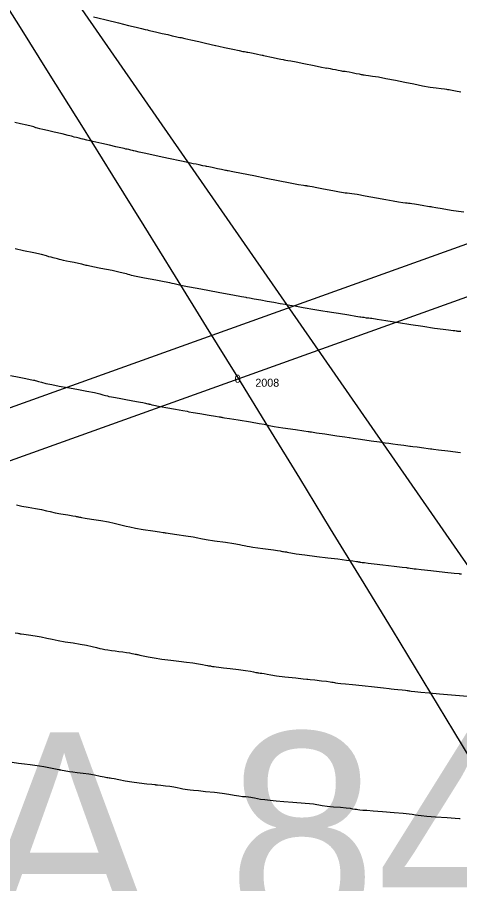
# Model space of a CAD drawing. Extents: x 74655 to 77873, y 48844 to 50507.
# Drawn here: x 75187.75 to 75194.38, y 49695.59 to 49708.57 of the extents above; entities that cross this region are included whole.
import ezdxf

# ---------------------------------------------------------------- set-up
doc = ezdxf.new("R2010")
doc.units = 0
for name, color, linetype in [('2', 7, 'Continuous'), ('24', 7, 'Continuous'), ('5', 7, 'Continuous'), ('50', 7, 'Continuous'), ('62', 7, 'Continuous'), ('7', 7, 'Continuous')]:
    doc.layers.add(name, color=color, linetype=linetype)

msp = doc.modelspace()

# ---------------------------------------------------------------- linework, layer by layer
at = {"layer": '2'}
for radius in [833.511, 829.511, 818.511]:
    msp.add_arc((74494.001, 49274.129), radius, 30.805045, 46.697858, dxfattribs=at)
at = {"layer": '5'}
msp.add_line((75166.591, 49740.588), (75280.568, 49576.243), dxfattribs=at)
at = {"layer": '50'}
for points in [[(75188.892, 49708.577), (75188.955, 49708.562), (75189.079, 49708.531), (75189.265, 49708.486), (75189.415, 49708.449), (75189.53, 49708.421), (75189.608, 49708.402), (75189.664, 49708.389), (75189.698, 49708.381), (75189.71, 49708.379), (75189.751, 49708.37), (75189.821, 49708.354), (75189.921, 49708.33), (75190.003, 49708.311), (75190.069, 49708.295), (75190.117, 49708.284), (75190.156, 49708.275), (75190.184, 49708.27), (75190.203, 49708.267), (75190.257, 49708.255), (75190.346, 49708.235), (75190.47, 49708.206), (75190.566, 49708.184), (75190.633, 49708.169), (75190.672, 49708.16), (75190.7, 49708.153), (75190.717, 49708.15), (75190.723, 49708.149), (75190.768, 49708.139), (75190.854, 49708.12), (75190.979, 49708.091), (75191.07, 49708.071), (75191.128, 49708.059), (75191.151, 49708.056), (75191.171, 49708.053), (75191.188, 49708.05), (75191.201, 49708.048), (75191.232, 49708.042), (75191.28, 49708.032), (75191.347, 49708.017), (75191.393, 49708.007), (75191.419, 49708.001), (75191.426, 49708.001), (75191.439, 49707.998), (75191.461, 49707.993), (75191.489, 49707.987), (75191.53, 49707.978), (75191.583, 49707.966), (75191.648, 49707.952), (75191.696, 49707.942), (75191.729, 49707.936), (75191.745, 49707.933), (75191.769, 49707.93), (75191.802, 49707.925), (75191.844, 49707.92), (75191.924, 49707.905), (75192.041, 49707.881), (75192.197, 49707.847), (75192.304, 49707.825), (75192.363, 49707.813), (75192.382, 49707.81)], [(75194.391, 49707.451), (75194.315, 49707.465), (75194.265, 49707.474), (75194.239, 49707.479), (75194.217, 49707.483), (75194.198, 49707.486), (75194.183, 49707.488), (75194.149, 49707.492), (75194.096, 49707.498), (75194.025, 49707.507), (75193.933, 49707.521), (75193.821, 49707.541), (75193.689, 49707.567), (75193.553, 49707.594), (75193.414, 49707.622), (75193.272, 49707.65), (75193.158, 49707.672), (75193.071, 49707.686), (75193.011, 49707.694), (75192.969, 49707.699), (75192.946, 49707.702), (75192.94, 49707.703), (75192.931, 49707.705), (75192.918, 49707.707), (75192.903, 49707.71), (75192.873, 49707.717), (75192.827, 49707.726), (75192.767, 49707.738), (75192.719, 49707.748), (75192.684, 49707.754), (75192.662, 49707.757), (75192.643, 49707.759), (75192.626, 49707.761), (75192.611, 49707.763), (75192.587, 49707.768), (75192.555, 49707.774), (75192.513, 49707.783), (75192.475, 49707.791), (75192.442, 49707.798), (75192.382, 49707.81)], [(75190.305, 49706.393), (75189.918, 49706.477), (75189.764, 49706.51), (75189.648, 49706.535), (75189.573, 49706.552), (75189.52, 49706.564), (75189.492, 49706.57), (75189.487, 49706.572), (75189.473, 49706.575), (75189.45, 49706.58), (75189.417, 49706.588), (75189.393, 49706.593), (75189.38, 49706.596), (75189.376, 49706.597), (75189.349, 49706.604), (75189.298, 49706.615), (75189.224, 49706.632), (75189.13, 49706.653), (75189.016, 49706.678), (75188.882, 49706.709), (75188.789, 49706.73), (75188.736, 49706.743), (75188.725, 49706.746), (75188.704, 49706.752), (75188.673, 49706.759), (75188.633, 49706.769), (75188.601, 49706.777), (75188.577, 49706.783), (75188.562, 49706.789), (75188.51, 49706.802), (75188.423, 49706.823), (75188.3, 49706.851), (75188.202, 49706.874), (75188.13, 49706.891), (75188.084, 49706.902), (75188.051, 49706.91), (75188.031, 49706.915), (75188.025, 49706.917), (75188.017, 49706.92), (75188.007, 49706.923), (75187.995, 49706.928), (75187.956, 49706.938), (75187.891, 49706.954), (75187.799, 49706.976), (75187.714, 49706.996)], [(75194.436, 49705.649), (75194.356, 49705.66), (75194.248, 49705.677), (75194.114, 49705.7), (75194.02, 49705.716), (75193.965, 49705.726), (75193.949, 49705.729), (75193.937, 49705.731), (75193.928, 49705.732), (75193.923, 49705.732), (75193.893, 49705.737), (75193.839, 49705.747), (75193.761, 49705.76), (75193.701, 49705.77), (75193.659, 49705.776), (75193.635, 49705.779), (75193.611, 49705.781), (75193.588, 49705.784), (75193.564, 49705.786), (75193.522, 49705.793), (75193.46, 49705.803), (75193.38, 49705.817), (75193.27, 49705.837), (75193.13, 49705.862), (75192.962, 49705.893), (75192.838, 49705.915), (75192.758, 49705.927), (75192.723, 49705.931), (75192.69, 49705.935), (75192.661, 49705.938), (75192.635, 49705.941), (75192.573, 49705.952), (75192.474, 49705.97), (75192.338, 49705.996), (75192.236, 49706.015), (75192.168, 49706.028), (75192.132, 49706.035), (75192.107, 49706.039), (75192.092, 49706.042), (75192.087, 49706.043), (75192.076, 49706.044), (75192.058, 49706.046), (75192.035, 49706.049), (75191.96, 49706.062), (75191.835, 49706.086), (75191.659, 49706.121), (75191.479, 49706.157), (75191.294, 49706.194), (75191.105, 49706.231), (75190.976, 49706.257), (75190.907, 49706.27), (75190.898, 49706.272), (75190.885, 49706.274), (75190.868, 49706.277), (75190.848, 49706.281), (75190.809, 49706.289), (75190.749, 49706.302), (75190.67, 49706.318), (75190.616, 49706.329), (75190.588, 49706.335), (75190.585, 49706.335), (75190.566, 49706.339), (75190.529, 49706.347), (75190.475, 49706.358), (75190.426, 49706.368), (75190.382, 49706.377), (75190.305, 49706.393)], [(75188.35, 49704.953), (75188.287, 49704.966), (75188.255, 49704.975), (75188.22, 49704.984), (75188.185, 49704.996), (75188.11, 49705.014), (75187.995, 49705.04), (75187.842, 49705.073), (75187.719, 49705.1)], [(75194.393, 49703.862), (75194.368, 49703.864), (75194.352, 49703.865), (75194.348, 49703.865), (75194.338, 49703.867), (75194.323, 49703.869), (75194.302, 49703.872), (75194.276, 49703.875), (75194.245, 49703.878), (75194.209, 49703.881), (75194.127, 49703.891), (75193.998, 49703.91), (75193.824, 49703.937), (75193.644, 49703.965), (75193.46, 49703.994), (75193.271, 49704.023), (75193.138, 49704.043), (75193.06, 49704.055), (75193.039, 49704.056), (75193.013, 49704.06), (75192.982, 49704.064), (75192.947, 49704.07), (75192.918, 49704.074), (75192.897, 49704.077), (75192.882, 49704.078), (75192.821, 49704.088), (75192.714, 49704.105), (75192.559, 49704.131), (75192.454, 49704.148), (75192.397, 49704.157), (75192.389, 49704.158), (75192.326, 49704.169), (75192.206, 49704.189), (75192.03, 49704.219), (75191.906, 49704.24), (75191.831, 49704.253), (75191.808, 49704.257), (75191.76, 49704.266), (75191.687, 49704.278), (75191.59, 49704.296), (75191.493, 49704.313), (75191.395, 49704.33), (75191.296, 49704.348), (75191.227, 49704.36), (75191.188, 49704.368), (75191.178, 49704.37), (75191.107, 49704.384), (75190.976, 49704.409), (75190.782, 49704.444), (75190.605, 49704.477), (75190.444, 49704.507), (75190.3, 49704.534), (75190.197, 49704.554), (75190.138, 49704.566), (75190.121, 49704.571), (75190.098, 49704.577), (75190.068, 49704.583), (75190.033, 49704.59), (75189.951, 49704.606), (75189.825, 49704.63), (75189.653, 49704.664), (75189.53, 49704.688), (75189.457, 49704.704), (75189.434, 49704.711), (75189.41, 49704.718), (75189.386, 49704.725), (75189.361, 49704.733), (75189.289, 49704.749), (75189.168, 49704.775), (75188.999, 49704.809), (75188.881, 49704.833), (75188.813, 49704.847), (75188.796, 49704.85), (75188.779, 49704.854), (75188.763, 49704.859), (75188.747, 49704.864), (75188.714, 49704.872), (75188.665, 49704.882), (75188.598, 49704.896), (75188.539, 49704.909), (75188.487, 49704.919), (75188.443, 49704.929), (75188.408, 49704.937), (75188.382, 49704.943), (75188.35, 49704.953)], [(75187.645, 49703.202), (75187.778, 49703.176), (75187.876, 49703.157), (75187.939, 49703.145), (75187.967, 49703.14), (75187.989, 49703.135), (75188.005, 49703.131), (75188.016, 49703.128), (75188.037, 49703.122), (75188.068, 49703.113), (75188.11, 49703.101), (75188.176, 49703.085), (75188.265, 49703.067), (75188.378, 49703.046), (75188.503, 49703.023), (75188.641, 49702.997), (75188.792, 49702.969), (75188.907, 49702.947), (75188.987, 49702.929), (75189.032, 49702.916), (75189.069, 49702.906), (75189.099, 49702.898), (75189.12, 49702.891), (75189.161, 49702.883), (75189.22, 49702.872), (75189.298, 49702.858), (75189.376, 49702.844), (75189.455, 49702.83), (75189.534, 49702.816), (75189.593, 49702.805), (75189.631, 49702.797), (75189.65, 49702.792), (75189.668, 49702.788), (75189.686, 49702.784), (75189.702, 49702.781), (75189.714, 49702.779), (75189.722, 49702.777), (75189.726, 49702.776), (75189.739, 49702.773), (75189.762, 49702.766), (75189.795, 49702.757), (75189.865, 49702.743), (75189.974, 49702.724), (75190.121, 49702.699), (75190.227, 49702.68), (75190.293, 49702.668), (75190.318, 49702.661), (75190.381, 49702.649), (75190.482, 49702.632), (75190.621, 49702.609), (75190.718, 49702.593), (75190.773, 49702.584), (75190.787, 49702.582), (75190.798, 49702.58), (75190.806, 49702.578), (75190.811, 49702.577), (75190.821, 49702.575), (75190.835, 49702.573), (75190.854, 49702.569), (75190.928, 49702.558), (75191.058, 49702.537), (75191.242, 49702.507), (75191.372, 49702.486), (75191.446, 49702.473), (75191.466, 49702.468), (75191.485, 49702.463), (75191.504, 49702.458), (75191.522, 49702.454), (75191.597, 49702.441), (75191.728, 49702.421), (75191.916, 49702.393), (75192.042, 49702.374), (75192.105, 49702.364), (75192.107, 49702.364), (75192.115, 49702.362), (75192.131, 49702.36), (75192.155, 49702.357), (75192.23, 49702.346), (75192.357, 49702.327), (75192.536, 49702.301), (75192.657, 49702.283), (75192.72, 49702.273), (75192.725, 49702.272), (75192.781, 49702.264), (75192.89, 49702.248), (75193.051, 49702.225), (75193.175, 49702.208), (75193.262, 49702.196), (75193.312, 49702.189), (75193.375, 49702.18), (75193.45, 49702.17), (75193.538, 49702.158), (75193.598, 49702.15), (75193.631, 49702.146), (75193.637, 49702.145), (75193.674, 49702.141), (75193.741, 49702.132), (75193.839, 49702.119), (75193.905, 49702.111), (75193.938, 49702.106), (75193.94, 49702.106), (75193.947, 49702.105), (75193.961, 49702.103), (75193.982, 49702.101), (75194.06, 49702.091), (75194.196, 49702.073), (75194.39, 49702.048)], [(75187.735, 49701.265), (75187.816, 49701.247), (75187.911, 49701.229), (75188.021, 49701.211), (75188.113, 49701.193), (75188.186, 49701.177), (75188.242, 49701.163), (75188.314, 49701.147), (75188.402, 49701.131), (75188.507, 49701.114), (75188.58, 49701.102), (75188.622, 49701.095), (75188.632, 49701.093), (75188.643, 49701.091), (75188.655, 49701.088), (75188.667, 49701.085), (75188.68, 49701.082), (75188.694, 49701.08), (75188.708, 49701.077), (75188.764, 49701.068), (75188.862, 49701.053), (75189.002, 49701.03), (75189.115, 49701.01), (75189.201, 49700.993), (75189.261, 49700.978), (75189.32, 49700.963), (75189.378, 49700.948), (75189.434, 49700.934), (75189.521, 49700.917), (75189.636, 49700.898), (75189.781, 49700.876), (75189.88, 49700.861), (75189.932, 49700.853), (75189.939, 49700.851), (75189.949, 49700.849), (75189.963, 49700.847), (75189.981, 49700.844), (75190.039, 49700.836), (75190.137, 49700.821), (75190.275, 49700.801), (75190.381, 49700.784), (75190.455, 49700.771), (75190.497, 49700.761), (75190.579, 49700.746), (75190.704, 49700.728), (75190.87, 49700.704), (75190.994, 49700.685), (75191.076, 49700.671), (75191.116, 49700.662), (75191.149, 49700.654), (75191.173, 49700.649), (75191.19, 49700.645), (75191.225, 49700.639), (75191.278, 49700.631), (75191.35, 49700.622), (75191.426, 49700.612), (75191.505, 49700.601), (75191.588, 49700.59), (75191.649, 49700.581), (75191.687, 49700.575), (75191.703, 49700.572), (75191.72, 49700.568), (75191.737, 49700.566), (75191.755, 49700.563), (75191.768, 49700.561), (75191.776, 49700.56), (75191.779, 49700.559), (75191.792, 49700.557), (75191.814, 49700.552), (75191.846, 49700.545), (75191.926, 49700.532), (75192.057, 49700.515), (75192.236, 49700.493), (75192.4, 49700.472), (75192.548, 49700.454), (75192.68, 49700.437), (75192.774, 49700.425), (75192.828, 49700.418), (75192.843, 49700.414), (75192.856, 49700.412), (75192.867, 49700.41), (75192.875, 49700.409), (75192.882, 49700.408), (75192.888, 49700.407), (75192.894, 49700.406), (75192.915, 49700.403), (75192.951, 49700.399), (75193.004, 49700.393), (75193.095, 49700.382), (75193.225, 49700.366), (75193.395, 49700.347), (75193.512, 49700.333), (75193.577, 49700.324), (75193.589, 49700.322), (75193.609, 49700.319), (75193.635, 49700.315), (75193.669, 49700.312), (75193.696, 49700.308), (75193.714, 49700.306), (75193.724, 49700.304), (75193.8, 49700.295), (75193.942, 49700.279), (75194.151, 49700.257), (75194.292, 49700.242), (75194.367, 49700.234), (75194.375, 49700.233), (75194.404, 49700.23)], [(75187.718, 49699.348), (75187.759, 49699.341), (75187.77, 49699.339), (75187.782, 49699.336), (75187.794, 49699.334), (75187.807, 49699.332), (75187.848, 49699.326), (75187.917, 49699.316), (75188.015, 49699.302), (75188.106, 49699.286), (75188.19, 49699.269), (75188.269, 49699.25), (75188.36, 49699.232), (75188.465, 49699.214), (75188.584, 49699.198), (75188.691, 49699.18), (75188.786, 49699.161), (75188.869, 49699.142), (75188.935, 49699.127), (75188.985, 49699.115), (75189.019, 49699.107), (75189.059, 49699.1), (75189.105, 49699.092), (75189.158, 49699.085), (75189.213, 49699.078), (75189.271, 49699.07), (75189.332, 49699.062), (75189.385, 49699.054), (75189.429, 49699.046), (75189.465, 49699.038), (75189.493, 49699.032), (75189.514, 49699.028), (75189.527, 49699.026), (75189.538, 49699.024), (75189.548, 49699.023), (75189.555, 49699.021), (75189.584, 49699.015), (75189.635, 49699.003), (75189.707, 49698.987), (75189.799, 49698.971), (75189.913, 49698.954), (75190.047, 49698.938), (75190.17, 49698.922), (75190.281, 49698.908), (75190.38, 49698.896), (75190.461, 49698.885), (75190.523, 49698.874), (75190.568, 49698.865), (75190.598, 49698.858), (75190.615, 49698.855), (75190.617, 49698.854), (75190.621, 49698.854), (75190.626, 49698.853), (75190.632, 49698.852), (75190.642, 49698.851), (75190.655, 49698.848), (75190.672, 49698.844), (75190.696, 49698.841), (75190.728, 49698.836), (75190.768, 49698.832), (75190.837, 49698.823), (75190.936, 49698.812), (75191.064, 49698.797), (75191.166, 49698.784), (75191.24, 49698.772), (75191.287, 49698.762), (75191.322, 49698.755), (75191.344, 49698.751), (75191.353, 49698.749), (75191.368, 49698.747), (75191.388, 49698.744), (75191.414, 49698.741), (75191.449, 49698.736), (75191.492, 49698.728), (75191.545, 49698.717), (75191.633, 49698.704), (75191.758, 49698.689), (75191.919, 49698.672), (75192.029, 49698.66), (75192.087, 49698.654), (75192.093, 49698.653), (75192.098, 49698.653), (75192.101, 49698.652), (75192.103, 49698.652), (75192.138, 49698.648), (75192.206, 49698.641), (75192.307, 49698.63), (75192.383, 49698.622), (75192.434, 49698.615), (75192.459, 49698.61), (75192.481, 49698.606), (75192.5, 49698.602), (75192.516, 49698.599), (75192.548, 49698.595), (75192.597, 49698.589), (75192.663, 49698.583), (75192.768, 49698.572), (75192.914, 49698.558), (75193.1, 49698.54), (75193.234, 49698.525), (75193.318, 49698.515), (75193.351, 49698.509), (75193.395, 49698.503), (75193.449, 49698.497), (75193.515, 49698.491), (75193.562, 49698.486), (75193.591, 49698.483), (75193.601, 49698.481), (75193.614, 49698.479), (75193.63, 49698.476), (75193.648, 49698.473), (75193.703, 49698.467), (75193.794, 49698.458), (75193.92, 49698.447), (75194.074, 49698.433), (75194.255, 49698.418), (75194.671, 49698.382)], [(75187.672, 49697.409), (75187.769, 49697.394), (75187.858, 49697.382), (75187.94, 49697.372), (75188.013, 49697.363), (75188.079, 49697.355), (75188.148, 49697.344), (75188.219, 49697.331), (75188.294, 49697.315), (75188.345, 49697.304), (75188.372, 49697.298), (75188.377, 49697.297), (75188.381, 49697.296), (75188.385, 49697.296), (75188.389, 49697.295), (75188.402, 49697.293), (75188.422, 49697.289), (75188.45, 49697.283), (75188.477, 49697.278), (75188.505, 49697.274), (75188.532, 49697.271), (75188.579, 49697.265), (75188.646, 49697.257), (75188.733, 49697.247), (75188.82, 49697.234), (75188.905, 49697.219), (75188.989, 49697.202), (75189.051, 49697.189), (75189.09, 49697.181), (75189.106, 49697.178), (75189.123, 49697.175), (75189.141, 49697.173), (75189.159, 49697.17), (75189.202, 49697.163), (75189.271, 49697.149), (75189.366, 49697.13), (75189.466, 49697.113), (75189.574, 49697.099), (75189.688, 49697.087), (75189.766, 49697.078), (75189.807, 49697.074), (75189.811, 49697.074), (75189.815, 49697.073), (75189.819, 49697.072), (75189.822, 49697.072), (75189.848, 49697.069), (75189.897, 49697.064), (75189.969, 49697.056), (75190.034, 49697.048), (75190.093, 49697.038), (75190.145, 49697.028), (75190.19, 49697.02), (75190.229, 49697.012), (75190.261, 49697.006), (75190.298, 49697), (75190.34, 49696.995), (75190.388, 49696.99), (75190.464, 49696.983), (75190.569, 49696.972), (75190.702, 49696.959), (75190.818, 49696.946), (75190.916, 49696.931), (75190.995, 49696.917), (75191.065, 49696.905), (75191.123, 49696.897), (75191.171, 49696.893), (75191.212, 49696.888), (75191.245, 49696.884), (75191.271, 49696.879), (75191.304, 49696.873), (75191.345, 49696.866), (75191.393, 49696.857), (75191.456, 49696.849), (75191.535, 49696.84), (75191.629, 49696.832), (75191.743, 49696.822), (75191.877, 49696.81), (75192.186, 49696.784)], [(75192.186, 49696.784), (75192.314, 49696.762), (75192.392, 49696.751), (75192.484, 49696.742), (75192.59, 49696.734), (75192.673, 49696.726), (75192.733, 49696.719), (75192.771, 49696.712), (75192.803, 49696.707), (75192.829, 49696.703), (75192.848, 49696.7), (75192.881, 49696.696), (75192.926, 49696.692), (75192.984, 49696.688), (75193.082, 49696.68), (75193.218, 49696.67), (75193.395, 49696.657), (75193.528, 49696.646), (75193.618, 49696.636), (75193.666, 49696.629), (75193.712, 49696.622), (75193.756, 49696.615), (75193.799, 49696.608), (75193.886, 49696.6), (75194.016, 49696.59), (75194.19, 49696.579), (75194.309, 49696.571), (75194.372, 49696.567), (75194.381, 49696.567)]]:
    msp.add_lwpolyline(points, dxfattribs=at)
at = {"layer": '7'}
for p, q in [((74992.787, 49632.792), (75369.276, 49767.909)), ((74993.04, 49632.087), (75369.529, 49767.203))]:
    msp.add_line(p, q, dxfattribs=at)

# ---------------------------------------------------------------- texts
at = {"layer": '24'}
msp.add_text('STA 84+26.80', height=3, dxfattribs=at).set_placement((75181.982, 49694.857))
at = {"layer": '62'}
for s, p in [('0', (75191.005, 49703.095)), ('2008', (75191.315, 49703.035))]:
    msp.add_text(s, height=0.12, dxfattribs=at).set_placement(p)

doc.saveas('drawing.dxf')
